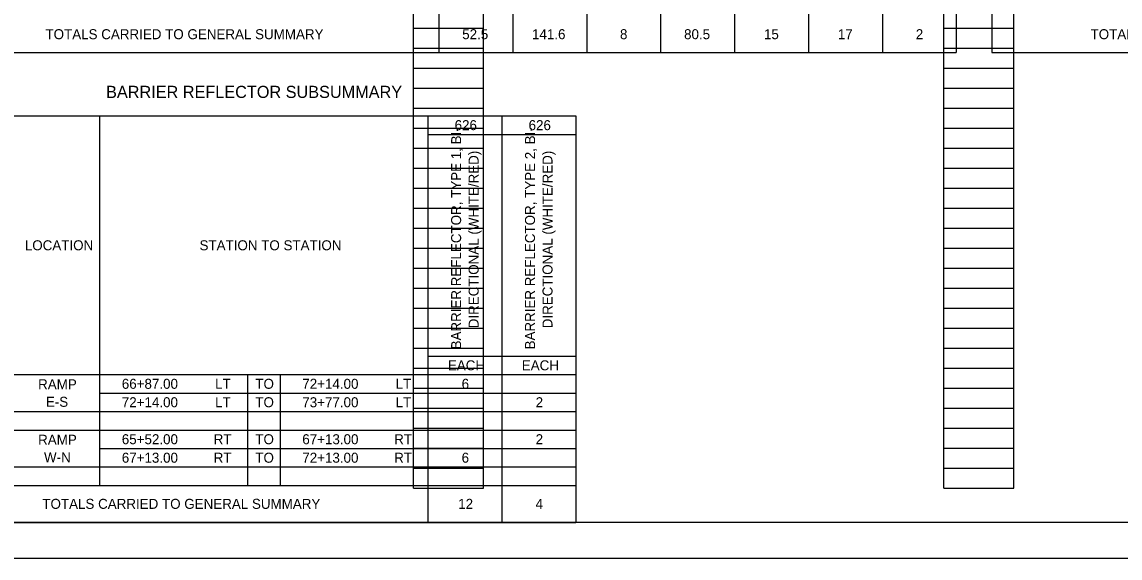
# Model space of a CAD drawing. Extents: x -6.8 to 34, y 0 to 22.
# Drawn here: x 3.36 to 18.73, y 0 to 7.51 of the extents above; entities that cross this region are included whole.
import ezdxf

# ---------------------------------------------------------------- set-up
doc = ezdxf.new("R2010")
doc.units = 0
for name, color, linetype in [('SH_Border', 7, 'Continuous'), ('SH_Cut_Line', 7, 'Continuous'), ('SH_Data', 7, 'Continuous'), ('SH_Text', 7, 'Continuous')]:
    doc.layers.add(name, color=color, linetype=linetype)

msp = doc.modelspace()

# ---------------------------------------------------------------- linework, layer by layer
at = {"layer": 'SH_Border'}
msp.add_lwpolyline([(1.5, 21.5), (33.5, 21.5), (33.5, 0.5), (1.5, 0.5)], close=True, dxfattribs=at)
at = {"layer": 'SH_Cut_Line'}
msp.add_lwpolyline([(0, 0), (34, 0), (34, 22), (0, 22)], close=True, dxfattribs=at)
at = {"layer": 'SH_Data'}
for p, q in [((8.84, 0.98), (8.84, 21.14)), ((9.82, 0.98), (9.82, 21.14)), ((16.26, 0.98), (16.26, 21.14)), ((17.24, 0.98), (17.24, 21.14)), ((8.84, 7.42), (9.82, 7.42)), ((16.26, 7.42), (17.24, 7.42)), ((8.84, 7.14), (9.82, 7.14)), ((16.26, 7.14), (17.24, 7.14)), ((8.84, 6.86), (9.82, 6.86)), ((16.26, 6.86), (17.24, 6.86)), ((8.84, 6.58), (9.82, 6.58)), ((16.26, 6.58), (17.24, 6.58)), ((8.84, 6.3), (9.82, 6.3)), ((16.26, 6.3), (17.24, 6.3)), ((8.84, 6.02), (9.82, 6.02)), ((16.26, 6.02), (17.24, 6.02)), ((8.84, 5.74), (9.82, 5.74)), ((16.26, 5.74), (17.24, 5.74)), ((8.84, 5.46), (9.82, 5.46)), ((16.26, 5.46), (17.24, 5.46)), ((8.84, 5.18), (9.82, 5.18)), ((16.26, 5.18), (17.24, 5.18)), ((8.84, 4.9), (9.82, 4.9)), ((16.26, 4.9), (17.24, 4.9)), ((8.84, 4.62), (9.82, 4.62)), ((16.26, 4.62), (17.24, 4.62)), ((8.84, 4.34), (9.82, 4.34)), ((16.26, 4.34), (17.24, 4.34)), ((8.84, 4.06), (9.82, 4.06)), ((16.26, 4.06), (17.24, 4.06)), ((8.84, 3.78), (9.82, 3.78)), ((16.26, 3.78), (17.24, 3.78)), ((8.84, 3.5), (9.82, 3.5)), ((16.26, 3.5), (17.24, 3.5)), ((8.84, 3.22), (9.82, 3.22)), ((16.26, 3.22), (17.24, 3.22)), ((8.84, 2.94), (9.82, 2.94)), ((16.26, 2.94), (17.24, 2.94)), ((8.84, 2.66), (9.82, 2.66)), ((16.26, 2.66), (17.24, 2.66)), ((8.84, 2.38), (9.82, 2.38)), ((16.26, 2.38), (17.24, 2.38)), ((8.84, 2.1), (9.82, 2.1)), ((16.26, 2.1), (17.24, 2.1)), ((8.84, 1.82), (9.82, 1.82)), ((16.26, 1.82), (17.24, 1.82)), ((8.84, 1.54), (9.82, 1.54)), ((16.26, 1.54), (17.24, 1.54)), ((8.84, 1.26), (9.82, 1.26)), ((16.26, 1.26), (17.24, 1.26)), ((8.84, 0.98), (9.82, 0.98)), ((16.26, 0.98), (17.24, 0.98))]:
    msp.add_line(p, q, dxfattribs=at)
at = {"layer": 'SH_Text'}
for p, q in [((9.192, 20.788), (9.192, 7.078)), ((10.227, 20.788), (10.227, 7.078)), ((11.262, 20.788), (11.262, 7.078)), ((12.296, 20.788), (12.296, 7.078)), ((13.331, 20.788), (13.331, 7.078)), ((14.366, 20.788), (14.366, 7.078)), ((15.401, 20.788), (15.401, 7.078)), ((16.435, 20.788), (16.435, 7.078)), ((16.932, 20.788), (16.932, 7.078)), ((1.872, 7.078), (16.435, 7.078)), ((16.932, 7.078), (31.662, 7.078)), ((1.872, 6.191), (11.109, 6.191)), ((4.444, 6.191), (4.444, 1.017)), ((9.04, 6.191), (9.04, 0.5)), ((10.075, 6.191), (10.075, 0.5)), ((11.109, 6.191), (11.109, 0.5)), ((9.04, 5.933), (11.109, 5.933)), ((9.04, 2.828), (11.109, 2.828)), ((1.872, 2.57), (11.109, 2.57)), ((6.514, 2.57), (6.514, 1.017)), ((6.97, 2.57), (6.97, 1.017)), ((4.444, 2.311), (11.109, 2.311)), ((1.872, 2.052), (11.109, 2.052)), ((1.872, 1.793), (11.109, 1.793)), ((4.444, 1.535), (11.109, 1.535)), ((1.872, 1.276), (11.109, 1.276)), ((1.872, 1.017), (11.109, 1.017)), ((1.872, 0.5), (11.109, 0.5))]:
    msp.add_line(p, q, dxfattribs=at)

# ---------------------------------------------------------------- texts
for s, height, p in [('TOTALS CARRIED TO GENERAL SUMMARY', 0.14, (3.688, 7.266)), ('52.5', 0.14, (9.52, 7.266)), ('141.6', 0.14, (10.497, 7.266)), ('8', 0.14, (11.728, 7.266)), ('80.5', 0.14, (12.625, 7.266)), ('15', 0.14, (13.743, 7.266)), ('17', 0.14, (14.777, 7.266)), ('2', 0.14, (15.868, 7.266)), ('TOTALS CARRIED TO GENERAL SUMMARY', 0.14, (18.314, 7.266)), ('BARRIER REFLECTOR SUBSUMMARY', 0.17, (4.536, 6.443)), ('626', 0.14, (9.414, 5.992)), ('626', 0.14, (10.449, 5.992)), ('LOCATION', 0.14, (3.399, 4.31)), ('STATION TO STATION', 0.14, (5.844, 4.31)), ('EACH', 0.14, (9.32, 2.629)), ('EACH', 0.14, (10.354, 2.629)), ('RAMP ', 0.14, (3.585, 2.363)), ('66+87.00', 0.14, (4.756, 2.37)), ('LT', 0.14, (6.062, 2.37)), ('TO', 0.14, (6.625, 2.37)), ('72+14.00', 0.14, (7.282, 2.37)), ('LT', 0.14, (8.588, 2.37)), ('6', 0.14, (9.512, 2.37)), ('E-S', 0.14, (3.693, 2.118)), ('72+14.00', 0.14, (4.756, 2.112)), ('LT', 0.14, (6.062, 2.112)), ('TO', 0.14, (6.625, 2.112)), ('73+77.00', 0.14, (7.282, 2.112)), ('LT', 0.14, (8.588, 2.112)), ('2', 0.14, (10.548, 2.112)), ('RAMP', 0.14, (3.585, 1.587)), ('65+52.00', 0.14, (4.756, 1.594)), ('RT', 0.14, (6.042, 1.594)), ('TO', 0.14, (6.625, 1.594)), ('67+13.00', 0.14, (7.282, 1.594)), ('RT', 0.14, (8.568, 1.594)), ('2', 0.14, (10.548, 1.594)), ('W-N', 0.14, (3.667, 1.342)), ('67+13.00', 0.14, (4.756, 1.335)), ('RT', 0.14, (6.042, 1.335)), ('TO', 0.14, (6.625, 1.335)), ('72+13.00', 0.14, (7.282, 1.335)), ('RT', 0.14, (8.568, 1.335)), ('6', 0.14, (9.512, 1.335)), ('TOTALS CARRIED TO GENERAL SUMMARY', 0.14, (3.644, 0.689)), ('12', 0.14, (9.464, 0.689)), ('4', 0.14, (10.547, 0.689))]:
    msp.add_text(s, height=height, dxfattribs=at).set_placement(p)
for s, p in [('BARRIER REFLECTOR, TYPE 1, BI-', (9.505, 2.922)), ('BARRIER REFLECTOR, TYPE 2, BI-', (10.539, 2.922)), ('DIRECTIONAL (WHITE/RED)', (9.75, 3.218)), ('DIRECTIONAL (WHITE/RED)', (10.784, 3.218))]:
    msp.add_text(s, height=0.14, rotation=90, dxfattribs=at).set_placement(p)

doc.saveas('drawing.dxf')
